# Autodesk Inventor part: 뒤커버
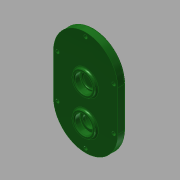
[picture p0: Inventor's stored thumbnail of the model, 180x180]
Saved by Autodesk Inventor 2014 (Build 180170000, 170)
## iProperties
Created: 2016-12
Part Number: 뒤커버
Material: 일반
Document SubType Name: Modeling
Designer: mduedu
Density: 1 g/cm^3
Appearance: Smooth - Dark Forest Green
Mass: 87.2434 g
Surface Area: 240.701 cm^2
Volume: 87.2434 cm^3
Author: mduedu
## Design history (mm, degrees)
sketch "스케치1"
  geometry: L1 (40, -25)-(40, 25); L2 (-40, 25)-(-40, -25); L3 (-40, -25)-(40, 25); L4 (40, -25)-(-40, 25); A1 r 40 centre (0, 25) between (40, 25) and (-40, 25); A2 r 40 centre (0, -25) between (-40, -25) and (40, -25); 1 further point
  constraints: 8 end point, 4 point on circle, 4 tangent, 2 centre point, 2 midpoint, 1 parallel, 1 vertical
  dimensions: "d0" = 130 dimension on A2 A1; "d2" = 80 distance between parallel lines of L1 L2
extrude "돌출1" new body sketch "스케치1" distance "d3" = 10; taper "d4" = 0 deg
sketch "스케치2"
  geometry: C1 r 14 at (0, 11); 1 further point
  constraints: 1 centre point, 1 vertical alignment
  dimensions: "d5" = 28 diameter of C1; "d6" = 11 distance of C1.centre point (0, 0)
extrude "돌출2" join sketch "스케치2" distance "d7" = 3; taper "d8" = 0 deg
sketch "스케치3"
  geometry: C1 r 14 at (0, -33.1); C2 r 14 at (0, 11) reference; 1 further point
  constraints: 1 centre point, 1 vertical alignment
  dimensions: "d9" = 28 diameter of C1; "d69" = 44.1 distance of C1.centre C2.centre
extrude "돌출3" join sketch "스케치3" distance "d11" = 3; taper "d12" = 0 deg
hole "구멍1" diameter "d15" = 22; stored, may be unused: countersink angle "d19" = 90 deg, drill point angle "d21" = 0 deg; dims "d13" = 10, "d14" = 10, "d16" = 6, "d17" = 4, "d18" = 2, "d20" = 7
hole "구멍2" diameter "d24" = 18; stored, may be unused: countersink angle "d28" = 90 deg, drill point angle "d30" = 0 deg; dims "d22" = 10, "d23" = 10, "d25" = 6, "d26" = 4, "d27" = 2, "d29" = 1
hole "구멍3" diameter "d33" = 22; stored, may be unused: countersink angle "d37" = 90 deg, drill point angle "d39" = 0 deg; dims "d31" = 10, "d32" = 10, "d34" = 6, "d35" = 4, "d36" = 2, "d38" = 7
sketch "스케치4"
  geometry: C1 r 14 at (0, -33.1) reference; C2 r 18 at (0, -33.1); 1 further point
  constraints: 1 centre point, 1 coincident
  dimensions: "d40" = 36 diameter of C2
extrude "돌출4" join sketch "스케치4" distance "d41" = 4; taper "d42" = 0 deg
hole "구멍4" diameter "d45" = 22; stored, may be unused: countersink angle "d49" = 90 deg, drill point angle "d51" = 0 deg; dims "d43" = 10, "d44" = 10, "d46" = 6, "d47" = 4, "d48" = 2, "d50" = 7
hole "구멍5" diameter "d54" = 15; stored, may be unused: countersink angle "d58" = 90 deg, drill point angle "d60" = 0 deg; dims "d52" = 10, "d53" = 10, "d55" = 6, "d56" = 4, "d57" = 2, "d59" = 7
fillet "모깎기1" dims "d61" = 0.3
fillet "모깎기2" dims "d62" = 2
chamfer "모따기1" distance "d63" = 1; stored, may be unused: second distance "d64" = 2, angle "d65" = 45 deg
fillet "모깎기3" dims "d66" = 2
fillet "모깎기4" dims "d67" = 2
fillet "모깎기5" dims "d68" = 2
sketch "스케치5"
  geometry: L1 (-40, 25)-(-40, -25) reference; L2 (40, -25)-(40, 25) reference; L3 (35, 25)-(35, -25); L4 (-35, -25)-(-35, 25); A1 r 40 centre (0, 25) between (40, 25) and (-40, 25) reference; A2 r 40 centre (0, -25) between (-40, -25) and (40, -25) reference; A3 r 35 centre (0, 25) between (35, 25) and (-35, 25); A4 r 35 centre (0, -25) between (-35, -25) and (35, -25); 2 further points
  constraints: 5 point on circle, 4 end point, 2 centre point, 1 vertical alignment, 3 other
  dimensions: "d70" = 5 distance between parallel lines of L2 L3
sketch "스케치6"
  geometry: 1 further point
hole "구멍6" sketch "스케치6" at (0, 60) diameter "d71" = 4.5; stored, may be unused: countersink angle "d75" = 90 deg, drill point angle "d77" = 0 deg; dims "d72" = 6, "d73" = 8, "d74" = 4.6, "d76" = 8
node "솔리드1"
pattern_linear "직사각형 패턴1"
